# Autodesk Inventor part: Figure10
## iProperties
Shininess: 77.0
Length Units: 11269
Angle Units: 11279
Time Units: 11290
Mass Units: 11283
Length Display Precision: 3
Angle Display Precision: 2
Created: 2002-01
Part Number: Figure10
Document SubType Name: Modeling
Designer: ***
Density: 0.0
Volumn: 0.0
Area: 0.0
PropertySet Name: Model Information
Control State: 0
Master: False
Checked Out: False
Author: ***
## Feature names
1. Extrusion1
2. Shell3
